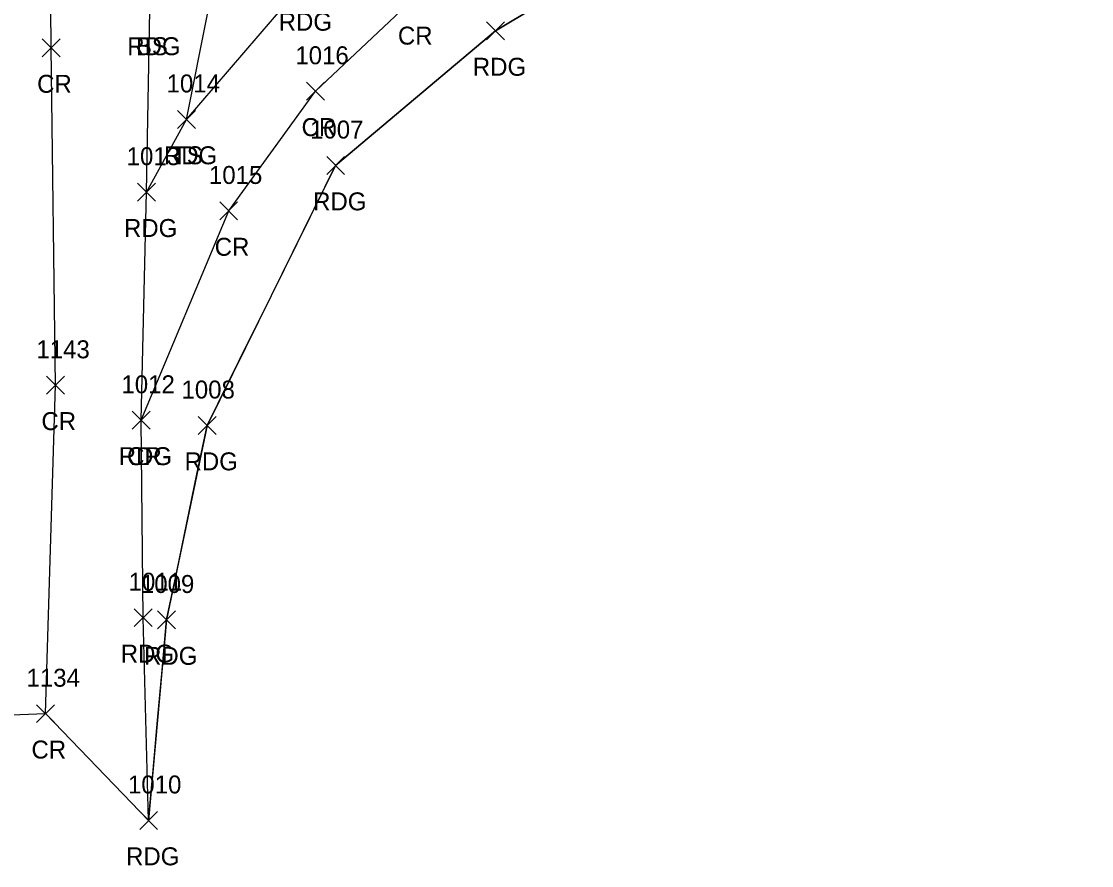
# Model space of a CAD drawing. Extents: x 1459992 to 1461532, y 647785 to 648535.
# Drawn here: x 1461396.4 to 1461515.7, y 647784.7 to 647878.7 of the extents above; entities that cross this region are included whole.
import ezdxf

# ---------------------------------------------------------------- set-up
doc = ezdxf.new("R2010")
doc.units = 0
for name, color, linetype in [('L_A', 7, 'Continuous'), ('L_I', 7, 'Continuous'), ('L_TIC', 7, 'Continuous'), ('LELB', 7, 'Continuous'), ('LSOGP', 7, 'Continuous'), ('P_A', 7, 'Continuous'), ('P_I', 7, 'Continuous'), ('P_TIC', 7, 'Continuous'), ('PEU', 7, 'Continuous'), ('PRC', 7, 'Continuous')]:
    doc.layers.add(name, color=color, linetype=linetype)

msp = doc.modelspace()

# ---------------------------------------------------------------- linework, layer by layer
at = {"layer": 'L_TIC'}
for points in [[(1461413.8, 647866.8), (1461415.8, 647868.8)], [(1461415.8, 647866.8), (1461413.8, 647868.8)]]:
    msp.add_lwpolyline(points, dxfattribs=at)
at = {"layer": 'LELB'}
msp.add_lwpolyline([(1461414.8, 647867.8), (1461419.56, 647891.67), (1461433.09, 647896.4), (1461451.97, 647902.77), (1461473.06, 647908.58), (1461481.61, 647907.91)], dxfattribs=at)
at = {"layer": 'LSOGP'}
msp.add_lwpolyline([(1461390.51, 647801.3), (1461399.1, 647801.61), (1461410.59, 647789.72), (1461411.09, 647795.3), (1461411.59, 647800.88), (1461412.09, 647806.46), (1461412.59, 647812.05), (1461413.72, 647817.46), (1461414.85, 647822.88), (1461415.97, 647828.29), (1461417.1, 647833.71), (1461420.68, 647840.95), (1461424.27, 647848.19), (1461427.85, 647855.43), (1461431.43, 647862.67), (1461435.88, 647866.42), (1461440.33, 647870.16), (1461444.78, 647873.91), (1461449.23, 647877.66), (1461453.77, 647880.38)], dxfattribs=at)
at = {"layer": 'P_TIC'}
for points in [[(1461448.23, 647876.66), (1461450.23, 647878.66)], [(1461450.23, 647876.66), (1461448.23, 647878.66)], [(1461398.73, 647874.76), (1461400.73, 647876.76)], [(1461400.73, 647874.76), (1461398.73, 647876.76)], [(1461428.2, 647869.94), (1461430.2, 647871.94)], [(1461430.2, 647869.94), (1461428.2, 647871.94)], [(1461413.8, 647866.8), (1461415.8, 647868.8)], [(1461415.8, 647866.8), (1461413.8, 647868.8)], [(1461430.43, 647861.67), (1461432.43, 647863.67)], [(1461432.43, 647861.67), (1461430.43, 647863.67)], [(1461409.35, 647858.7), (1461411.35, 647860.7)], [(1461411.35, 647858.7), (1461409.35, 647860.7)], [(1461409.35, 647858.7), (1461411.35, 647860.7)], [(1461411.35, 647858.7), (1461409.35, 647860.7)], [(1461418.51, 647856.61), (1461420.51, 647858.61)], [(1461420.51, 647856.61), (1461418.51, 647858.61)], [(1461399.2, 647837.19), (1461401.2, 647839.19)], [(1461401.2, 647837.19), (1461399.2, 647839.19)], [(1461408.76, 647833.29), (1461410.76, 647835.29)], [(1461410.76, 647833.29), (1461408.76, 647835.29)], [(1461408.76, 647833.29), (1461410.76, 647835.29)], [(1461410.76, 647833.29), (1461408.76, 647835.29)], [(1461416.1, 647832.71), (1461418.1, 647834.71)], [(1461418.1, 647832.71), (1461416.1, 647834.71)], [(1461408.99, 647811.3), (1461410.99, 647813.3)], [(1461410.99, 647811.3), (1461408.99, 647813.3)], [(1461411.59, 647811.05), (1461413.59, 647813.05)], [(1461413.59, 647811.05), (1461411.59, 647813.05)], [(1461398.1, 647800.61), (1461400.1, 647802.61)], [(1461400.1, 647800.61), (1461398.1, 647802.61)], [(1461409.59, 647788.72), (1461411.59, 647790.72)], [(1461411.59, 647788.72), (1461409.59, 647790.72)]]:
    msp.add_lwpolyline(points, dxfattribs=at)
at = {"layer": 'PEU'}
for points in [[(1461511.7, 647896.63), (1461486.75, 647893.93), (1461467.39, 647888.55), (1461449.23, 647877.66), (1461431.43, 647862.67), (1461417.1, 647833.71), (1461412.59, 647812.05), (1461410.59, 647789.72), (1461409.99, 647812.3), (1461409.76, 647834.29), (1461410.35, 647859.7), (1461410.72, 647879.95), (1461409.82, 647907.07), (1461410.46, 647924.41), (1461409.73, 647942.58), (1461408.16, 647966.3), (1461407.05, 647997.1), (1461405.27, 648031.27), (1461404.3, 648042.52)], [(1461410.35, 647859.7), (1461414.8, 647867.8), (1461427.6, 647882.68), (1461437.9, 647891.82), (1461455.84, 647900.41), (1461474.57, 647905.24), (1461481.61, 647907.91), (1461493.49, 647909.89), (1461478.08, 647912.96), (1461461.54, 647921.45), (1461453.81, 647925.91), (1461445.97, 647927.18), (1461431.98, 647933.27), (1461420.49, 647932.44), (1461410.46, 647924.41)]]:
    msp.add_lwpolyline(points, dxfattribs=at)
at = {"layer": 'PRC'}
for points in [[(1461399.1, 647801.61), (1461400.2, 647838.19), (1461399.73, 647875.76), (1461399.54, 647898.4), (1461398.45, 647928.21), (1461395.01, 647961.97), (1461394.12, 647993.81), (1461392.15, 648024.04), (1461390.38, 648057.37), (1461388.52, 648080.66), (1461387.02, 648100.03), (1461383.87, 648115.79), (1461378.35, 648129.27), (1461372.21, 648140.65), (1461365.44, 648150.97), (1461358.13, 648158.61)], [(1461409.76, 647834.29), (1461419.51, 647857.61), (1461429.2, 647870.94), (1461439.94, 647881.13), (1461459.44, 647893.97), (1461476.69, 647898.52), (1461483.02, 647900.51), (1461497.87, 647903.57), (1461515.67, 647905.41)]]:
    msp.add_lwpolyline(points, dxfattribs=at)

# ---------------------------------------------------------------- texts
at = {"layer": 'L_A'}
for s, p in [('BS', (1461409.17, 647874.95)), ('TS', (1461413.21, 647862.8))]:
    msp.add_text(s, height=2, dxfattribs=at).set_placement(p)
at = {"layer": 'L_I'}
msp.add_text('1014', height=2, dxfattribs=at).set_placement((1461412.59, 647870.8))
at = {"layer": 'P_A'}
for s, p in [('RDG', (1461425.08, 647877.68)), ('CR', (1461438.37, 647876.13)), ('RDG', (1461408.21, 647874.95)), ('RDG', (1461446.72, 647872.66)), ('CR', (1461398.16, 647870.76)), ('CR', (1461427.63, 647865.94)), ('RDG', (1461412.29, 647862.8)), ('RDG', (1461428.92, 647857.67)), ('RDG', (1461407.84, 647854.7)), ('RDG', (1461407.84, 647854.7)), ('CR', (1461417.95, 647852.61)), ('CR', (1461398.64, 647833.19)), ('RDG', (1461407.25, 647829.29)), ('CR', (1461408.19, 647829.29)), ('RDG', (1461414.59, 647828.71)), ('RDG', (1461407.48, 647807.3)), ('RDG', (1461410.08, 647807.05)), ('CR', (1461397.53, 647796.61)), ('RDG', (1461408.07, 647784.72))]:
    msp.add_text(s, height=2, dxfattribs=at).set_placement(p)
at = {"layer": 'P_I'}
for s, p in [('1016', (1461426.94, 647873.94)), ('1014', (1461412.59, 647870.8)), ('1007', (1461428.58, 647865.67)), ('1013', (1461408.14, 647862.7)), ('1013', (1461408.14, 647862.7)), ('1015', (1461417.31, 647860.61)), ('1143', (1461398.08, 647841.19)), ('1012', (1461407.56, 647837.29)), ('1012', (1461407.56, 647837.29)), ('1008', (1461414.25, 647836.71)), ('1011', (1461408.36, 647815.3)), ('1009', (1461409.73, 647815.05)), ('1134', (1461396.98, 647804.61)), ('1010', (1461408.29, 647792.72))]:
    msp.add_text(s, height=2, dxfattribs=at).set_placement(p)

doc.saveas('drawing.dxf')
